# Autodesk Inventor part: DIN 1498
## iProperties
Company: Bakker Hydraulic B.V.
Shininess: 64.0
Length Units: 11269
Angle Units: 11279
Time Units: 11290
Mass Units: 11283
Length Display Precision: 3
Angle Display Precision: 2
Compacted: True
Part Number: DIN 1498
Document SubType Name: Modeling
Created: 2003-01
Designer: Cor J. de Vlaming
Engineer: Cor de Vlaming
Material: 55Si7
Description: DIN 1498 - EG 50/40 x 60
Density: 0.0
Volumn: 0.0
Area: 0.0
PropertySet Name: Model Information
Control State: 0
Master: False
Checked Out: False
Author: Cor J. de Vlaming
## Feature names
1. Extrusion1
2. Chamfer1
3. Fillet1
